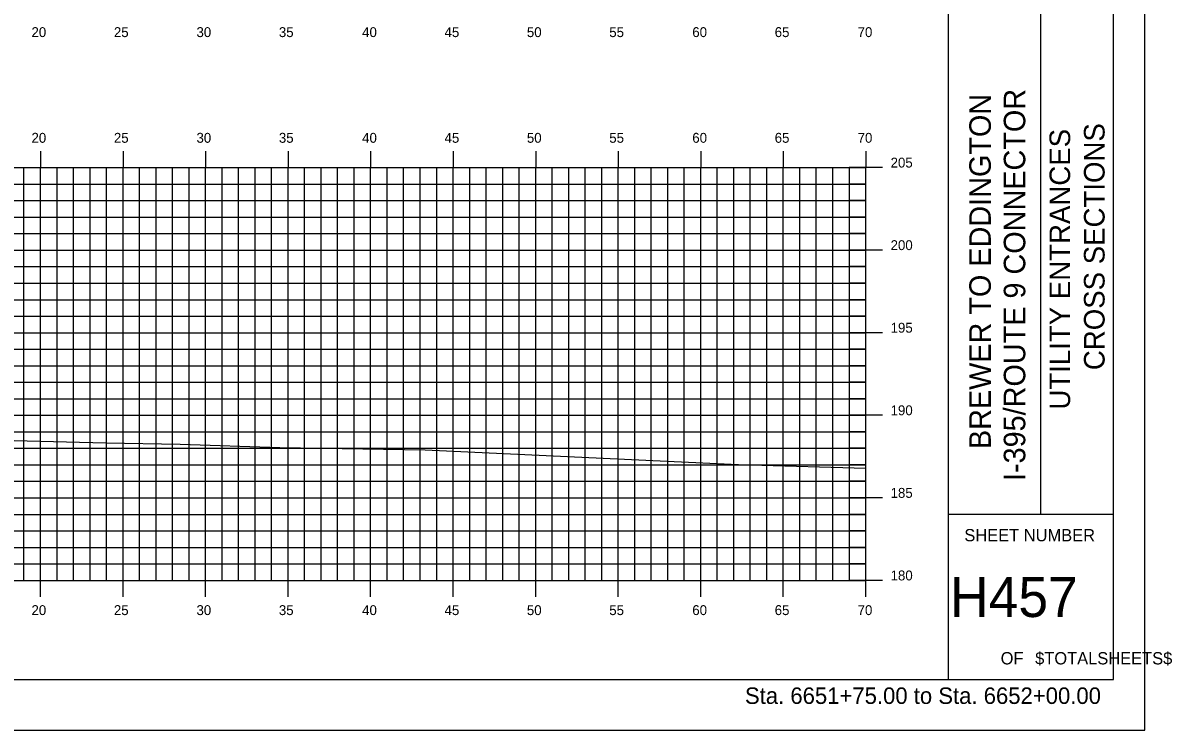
# Model space of a CAD drawing. Extents: x 1723764 to 1723936, y 458501 to 458611.
# Drawn here: x 1723866.5 to 1723936.1, y 458501.2 to 458544 of the extents above; entities that cross this region are included whole.
import ezdxf

# ---------------------------------------------------------------- set-up
doc = ezdxf.new("R2010")
doc.units = 0
for name, color, linetype in [('BORDER', 7, 'Continuous'), ('H_V ANNOTATION', 7, 'Continuous'), ('HIGHWAY_TITLE', 7, 'Continuous'), ('MAJOR', 7, 'Continuous'), ('MINOR', 7, 'Continuous'), ('PLOT BOUNDARY', 7, 'Continuous'), ('S_Roadway_Centerline', 7, 'Continuous')]:
    doc.layers.add(name, color=color, linetype=linetype)

msp = doc.modelspace()

# ---------------------------------------------------------------- linework, layer by layer
at = {"layer": 'BORDER'}
for p, q in [((1723922.542, 458504.254), (1723922.542, 458609.254)), ((1723928.133, 458514.257), (1723928.133, 458549.257)), ((1723922.542, 458514.257), (1723932.542, 458514.257))]:
    msp.add_line(p, q, dxfattribs=at)
msp.add_lwpolyline([(1723772.542, 458504.254), (1723932.542, 458504.254), (1723932.542, 458609.254), (1723772.542, 458609.254)], close=True, dxfattribs=at)
at = {"layer": 'MAJOR'}
for p, q in [((1723867.542, 458536.256), (1723867.542, 458535.254)), ((1723872.542, 458536.256), (1723872.542, 458535.254)), ((1723877.542, 458536.256), (1723877.542, 458535.254)), ((1723882.542, 458536.256), (1723882.542, 458535.254)), ((1723887.542, 458536.256), (1723887.542, 458535.254)), ((1723892.542, 458536.256), (1723892.542, 458535.254)), ((1723897.542, 458536.256), (1723897.542, 458535.254)), ((1723902.542, 458536.256), (1723902.542, 458535.254)), ((1723907.542, 458536.256), (1723907.542, 458535.254)), ((1723912.542, 458536.256), (1723912.542, 458535.254)), ((1723917.542, 458536.256), (1723917.542, 458535.254)), ((1723777.542, 458535.254), (1723917.542, 458535.254)), ((1723777.542, 458535.254), (1723917.542, 458535.254)), ((1723867.542, 458510.254), (1723867.542, 458535.254)), ((1723872.542, 458510.254), (1723872.542, 458535.254)), ((1723877.542, 458510.254), (1723877.542, 458535.254)), ((1723882.542, 458510.254), (1723882.542, 458535.254)), ((1723887.542, 458510.254), (1723887.542, 458535.254)), ((1723892.542, 458510.254), (1723892.542, 458535.254)), ((1723897.542, 458510.254), (1723897.542, 458535.254)), ((1723902.542, 458510.254), (1723902.542, 458535.254)), ((1723907.542, 458510.254), (1723907.542, 458535.254)), ((1723912.542, 458510.254), (1723912.542, 458535.254)), ((1723918.544, 458535.254), (1723916.54, 458535.254)), ((1723917.542, 458510.254), (1723917.542, 458535.254)), ((1723917.542, 458510.254), (1723917.542, 458535.254)), ((1723777.542, 458530.254), (1723917.542, 458530.254)), ((1723918.544, 458530.254), (1723916.54, 458530.254)), ((1723777.542, 458525.254), (1723917.542, 458525.254)), ((1723918.544, 458525.254), (1723916.54, 458525.254)), ((1723777.542, 458520.254), (1723917.542, 458520.254)), ((1723918.544, 458520.254), (1723916.54, 458520.254)), ((1723777.542, 458515.254), (1723917.542, 458515.254)), ((1723918.544, 458515.254), (1723916.54, 458515.254)), ((1723777.542, 458510.254), (1723917.542, 458510.254)), ((1723777.542, 458510.254), (1723917.542, 458510.254)), ((1723867.542, 458509.252), (1723867.542, 458510.254)), ((1723872.542, 458509.252), (1723872.542, 458510.254)), ((1723877.542, 458509.252), (1723877.542, 458510.254)), ((1723882.542, 458509.252), (1723882.542, 458510.254)), ((1723887.542, 458509.252), (1723887.542, 458510.254)), ((1723892.542, 458509.252), (1723892.542, 458510.254)), ((1723897.542, 458509.252), (1723897.542, 458510.254)), ((1723902.542, 458509.252), (1723902.542, 458510.254)), ((1723907.542, 458509.252), (1723907.542, 458510.254)), ((1723912.542, 458509.252), (1723912.542, 458510.254)), ((1723918.544, 458510.254), (1723916.54, 458510.254)), ((1723917.542, 458509.252), (1723917.542, 458510.254))]:
    msp.add_line(p, q, dxfattribs=at)
at = {"layer": 'MINOR'}
for p, q in [((1723866.542, 458510.254), (1723866.542, 458535.254)), ((1723868.542, 458510.254), (1723868.542, 458535.254)), ((1723869.542, 458510.254), (1723869.542, 458535.254)), ((1723870.542, 458510.254), (1723870.542, 458535.254)), ((1723871.542, 458510.254), (1723871.542, 458535.254)), ((1723873.542, 458510.254), (1723873.542, 458535.254)), ((1723874.542, 458510.254), (1723874.542, 458535.254)), ((1723875.542, 458510.254), (1723875.542, 458535.254)), ((1723876.542, 458510.254), (1723876.542, 458535.254)), ((1723878.542, 458510.254), (1723878.542, 458535.254)), ((1723879.542, 458510.254), (1723879.542, 458535.254)), ((1723880.542, 458510.254), (1723880.542, 458535.254)), ((1723881.542, 458510.254), (1723881.542, 458535.254)), ((1723883.542, 458510.254), (1723883.542, 458535.254)), ((1723884.542, 458510.254), (1723884.542, 458535.254)), ((1723885.542, 458510.254), (1723885.542, 458535.254)), ((1723886.542, 458510.254), (1723886.542, 458535.254)), ((1723888.542, 458510.254), (1723888.542, 458535.254)), ((1723889.542, 458510.254), (1723889.542, 458535.254)), ((1723890.542, 458510.254), (1723890.542, 458535.254)), ((1723891.542, 458510.254), (1723891.542, 458535.254)), ((1723893.542, 458510.254), (1723893.542, 458535.254)), ((1723894.542, 458510.254), (1723894.542, 458535.254)), ((1723895.542, 458510.254), (1723895.542, 458535.254)), ((1723896.542, 458510.254), (1723896.542, 458535.254)), ((1723898.542, 458510.254), (1723898.542, 458535.254)), ((1723899.542, 458510.254), (1723899.542, 458535.254)), ((1723900.542, 458510.254), (1723900.542, 458535.254)), ((1723901.542, 458510.254), (1723901.542, 458535.254)), ((1723903.542, 458510.254), (1723903.542, 458535.254)), ((1723904.542, 458510.254), (1723904.542, 458535.254)), ((1723905.542, 458510.254), (1723905.542, 458535.254)), ((1723906.542, 458510.254), (1723906.542, 458535.254)), ((1723908.542, 458510.254), (1723908.542, 458535.254)), ((1723909.542, 458510.254), (1723909.542, 458535.254)), ((1723910.542, 458510.254), (1723910.542, 458535.254)), ((1723911.542, 458510.254), (1723911.542, 458535.254)), ((1723913.542, 458510.254), (1723913.542, 458535.254)), ((1723914.542, 458510.254), (1723914.542, 458535.254)), ((1723915.542, 458510.254), (1723915.542, 458535.254)), ((1723916.542, 458510.254), (1723916.542, 458535.254)), ((1723777.542, 458534.254), (1723917.542, 458534.254)), ((1723917.542, 458534.254), (1723916.54, 458534.254)), ((1723777.542, 458533.254), (1723917.542, 458533.254)), ((1723917.542, 458533.254), (1723916.54, 458533.254)), ((1723777.542, 458532.254), (1723917.542, 458532.254)), ((1723917.542, 458532.254), (1723916.54, 458532.254)), ((1723777.542, 458531.254), (1723917.542, 458531.254)), ((1723917.542, 458531.254), (1723916.54, 458531.254)), ((1723777.542, 458529.254), (1723917.542, 458529.254)), ((1723917.542, 458529.254), (1723916.54, 458529.254)), ((1723777.542, 458528.254), (1723917.542, 458528.254)), ((1723917.542, 458528.254), (1723916.54, 458528.254)), ((1723777.542, 458527.254), (1723917.542, 458527.254)), ((1723917.542, 458527.254), (1723916.54, 458527.254)), ((1723777.542, 458526.254), (1723917.542, 458526.254)), ((1723917.542, 458526.254), (1723916.54, 458526.254)), ((1723777.542, 458524.254), (1723917.542, 458524.254)), ((1723917.542, 458524.254), (1723916.54, 458524.254)), ((1723777.542, 458523.254), (1723917.542, 458523.254)), ((1723917.542, 458523.254), (1723916.54, 458523.254)), ((1723777.542, 458522.254), (1723917.542, 458522.254)), ((1723917.542, 458522.254), (1723916.54, 458522.254)), ((1723777.542, 458521.254), (1723917.542, 458521.254)), ((1723917.542, 458521.254), (1723916.54, 458521.254)), ((1723777.542, 458519.254), (1723917.542, 458519.254)), ((1723917.542, 458519.254), (1723916.54, 458519.254)), ((1723777.542, 458518.254), (1723917.542, 458518.254)), ((1723917.542, 458518.254), (1723916.54, 458518.254)), ((1723777.542, 458517.254), (1723917.542, 458517.254)), ((1723917.542, 458517.254), (1723916.54, 458517.254)), ((1723777.542, 458516.254), (1723917.542, 458516.254)), ((1723917.542, 458516.254), (1723916.54, 458516.254)), ((1723777.542, 458514.254), (1723917.542, 458514.254)), ((1723917.542, 458514.254), (1723916.54, 458514.254)), ((1723777.542, 458513.254), (1723917.542, 458513.254)), ((1723917.542, 458513.254), (1723916.54, 458513.254)), ((1723777.542, 458512.254), (1723917.542, 458512.254)), ((1723917.542, 458512.254), (1723916.54, 458512.254)), ((1723777.542, 458511.254), (1723917.542, 458511.254)), ((1723917.542, 458511.254), (1723916.54, 458511.254))]:
    msp.add_line(p, q, dxfattribs=at)
at = {"layer": 'PLOT BOUNDARY'}
msp.add_lwpolyline([(1723764.449, 458501.195), (1723934.449, 458501.195), (1723934.449, 458611.195), (1723764.449, 458611.195)], close=True, dxfattribs=at)
at = {"layer": 'S_Roadway_Centerline'}
msp.add_lwpolyline([(1723777.542, 458521.199), (1723779.498, 458521.105), (1723791.306, 458521.409), (1723791.899, 458521.4), (1723792.275, 458521.382), (1723804.058, 458520.64), (1723811.145, 458520.252), (1723821.989, 458519.841), (1723830.395, 458519.783), (1723837.603, 458519.852), (1723851.939, 458519.531), (1723853.337, 458519.47), (1723862.761, 458518.803), (1723871.493, 458518.59), (1723876.01, 458518.494), (1723882.047, 458518.307), (1723890.843, 458518.155), (1723910.242, 458517.258), (1723910.291, 458517.255), (1723910.542, 458517.248), (1723917.542, 458517.046)], dxfattribs=at)

# ---------------------------------------------------------------- texts
at = {"layer": 'BORDER'}
for s, p in [('CROSS SECTIONS', (1723932.006, 458522.988)), ('UTILITY ENTRANCES', (1723929.919, 458520.597))]:
    msp.add_text(s, height=1.25, rotation=90, dxfattribs=at).set_placement(p)
for s, height, p in [('SHEET NUMBER', 0.74527, (1723923.508, 458512.621)), ('H457', 2.4194, (1723922.647, 458508.037)), ('OF', 0.7453, (1723925.709, 458505.167)), ('$TOTALSHEETS$', 0.74527, (1723927.799, 458505.167))]:
    msp.add_text(s, height=height, dxfattribs=at).set_placement(p)
at = {"layer": 'H_V ANNOTATION'}
for s, height, p in [('20', 0.6, (1723866.996, 458543.154)), ('25', 0.6, (1723871.988, 458543.154)), ('30', 0.6, (1723876.991, 458543.154)), ('35', 0.6, (1723881.983, 458543.154)), ('40', 0.6, (1723887.028, 458543.154)), ('45', 0.6, (1723892.02, 458543.154)), ('50', 0.6, (1723897.007, 458543.154)), ('55', 0.6, (1723901.999, 458543.154)), ('60', 0.6, (1723907.028, 458543.154)), ('65', 0.6, (1723912.02, 458543.154)), ('70', 0.6, (1723917.044, 458543.154)), ('20', 0.6, (1723866.996, 458536.754)), ('25', 0.6, (1723871.988, 458536.754)), ('30', 0.6, (1723876.991, 458536.754)), ('35', 0.6, (1723881.983, 458536.754)), ('40', 0.6, (1723887.028, 458536.754)), ('45', 0.6, (1723892.02, 458536.754)), ('50', 0.6, (1723897.007, 458536.754)), ('55', 0.6, (1723901.999, 458536.754)), ('60', 0.6, (1723907.028, 458536.754)), ('65', 0.6, (1723912.02, 458536.754)), ('70', 0.6, (1723917.044, 458536.754)), ('205', 0.6, (1723919.042, 458535.254)), ('200', 0.6, (1723919.042, 458530.254)), ('195', 0.6, (1723919.042, 458525.254)), ('190', 0.6, (1723919.042, 458520.254)), ('185', 0.6, (1723919.042, 458515.254)), ('180', 0.6, (1723919.042, 458510.254)), ('20', 0.6, (1723866.996, 458508.154)), ('25', 0.6, (1723871.988, 458508.154)), ('30', 0.6, (1723876.991, 458508.154)), ('35', 0.6, (1723881.983, 458508.154)), ('40', 0.6, (1723887.028, 458508.154)), ('45', 0.6, (1723892.02, 458508.154)), ('50', 0.6, (1723897.007, 458508.154)), ('55', 0.6, (1723901.999, 458508.154)), ('60', 0.6, (1723907.028, 458508.154)), ('65', 0.6, (1723912.02, 458508.154)), ('70', 0.6, (1723917.044, 458508.154)), ('Sta. 6651+75.00 to Sta. 6652+00.00', 1.0002, (1723910.218, 458502.774))]:
    msp.add_text(s, height=height, dxfattribs=at).set_placement(p)
at = {"layer": 'HIGHWAY_TITLE'}
for s, p in [('I-395/ROUTE 9 CONNECTOR', (1723927.201, 458516.273)), ('BREWER TO EDDINGTON', (1723925.114, 458518.206))]:
    msp.add_text(s, height=1.30428, rotation=90, dxfattribs=at).set_placement(p)

doc.saveas('drawing.dxf')
